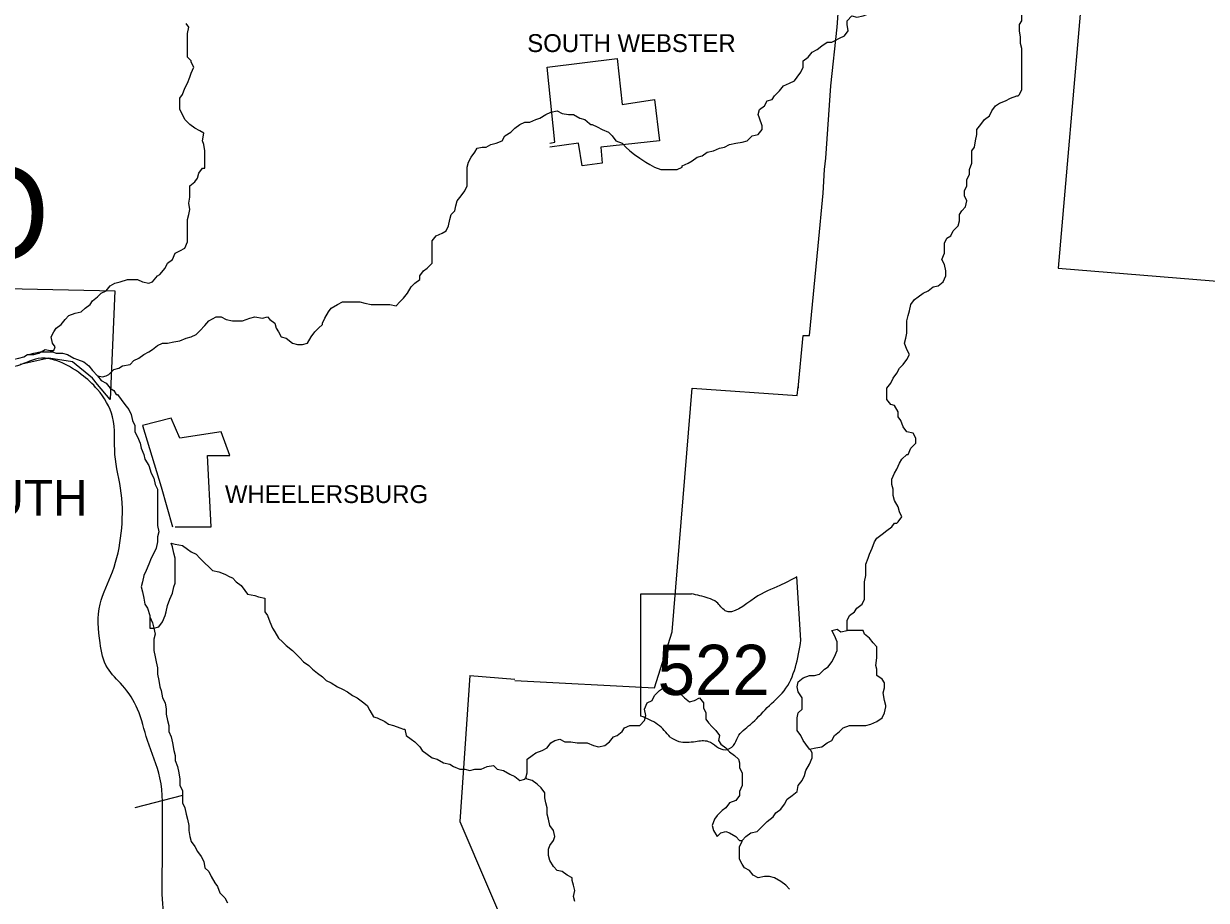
# Model space of a CAD drawing. Extents: x 0 to 40.2, y 0 to 22.
# Drawn here: x 6.366 to 7.657, y 15.911 to 16.868 of the extents above; entities that cross this region are included whole.
import ezdxf

# ---------------------------------------------------------------- set-up
doc = ezdxf.new("R2010")
doc.units = 0
doc.layers.add('Default', color=7, linetype='Continuous')
doc.layers.add('TR_Turning_Path1', color=7, linetype='Continuous')

msp = doc.modelspace()

# ---------------------------------------------------------------- linework, layer by layer
at = {"layer": 'Default'}
msp.add_line((7.0546, 16.1427), (7.0546, 16.1427), dxfattribs=at)
for points in [[(7.2114, 16.4699), (7.2169, 16.5272), (7.2237, 16.5272), (7.2332, 16.6253), (7.2387, 16.6826), (7.2401, 16.7085), (7.2414, 16.7208), (7.2469, 16.7998), (7.2537, 16.8639), (7.2578, 16.9198), (7.2578, 16.9198), (7.2578, 16.9198)], [(7.251, 16.8489), (7.2564, 16.8517), (7.2619, 16.8544), (7.266, 16.8598), (7.2646, 16.8667), (7.2646, 16.8707), (7.27, 16.8762), (7.2755, 16.8748), (7.2823, 16.8762), (7.2891, 16.8789), (7.2919, 16.883), (7.2973, 16.8844), (7.3055, 16.8871), (7.3109, 16.8885), (7.3164, 16.8926), (7.3164, 16.8994), (7.3219, 16.9035), (7.3232, 16.9103), (7.3246, 16.9116), (7.3246, 16.913)], [(7.4527, 16.7903), (7.4555, 16.7958), (7.4555, 16.8026), (7.4555, 16.8094), (7.4555, 16.8148), (7.4555, 16.8217), (7.4555, 16.8271), (7.4555, 16.8339), (7.4555, 16.8407), (7.4541, 16.8462), (7.4541, 16.853), (7.4527, 16.8598), (7.4527, 16.8667), (7.4555, 16.8707), (7.4555, 16.8789), (7.4555, 16.8844), (7.4527, 16.8885), (7.45, 16.8953), (7.4473, 16.9007), (7.4446, 16.9035), (7.4432, 16.9035)], [(7.5209, 16.8994), (7.495, 16.6008), (7.8468, 16.5722), (7.8372, 16.4385), (7.9054, 16.4331), (7.8918, 16.2599), (7.8849, 16.1645), (8.2163, 16.144), (8.2544, 16.1399), (8.3035, 16.1372)], [(6.5488, 16.8271), (6.5447, 16.8312), (6.5447, 16.838), (6.5447, 16.8435), (6.5447, 16.8517), (6.5447, 16.8571), (6.5461, 16.8639), (6.5433, 16.868)], [(7.1828, 16.7848), (7.1855, 16.7889), (7.191, 16.7944), (7.1951, 16.7998), (7.2019, 16.8026), (7.2073, 16.8053), (7.2101, 16.8094), (7.2141, 16.8148), (7.2169, 16.8203), (7.2169, 16.8271), (7.2223, 16.8312), (7.2264, 16.8367), (7.2319, 16.8394), (7.2373, 16.8435), (7.2428, 16.8476), (7.2482, 16.8476), (7.251, 16.8489)], [(6.5638, 16.7099), (6.5638, 16.7167), (6.5638, 16.7221), (6.5638, 16.7289), (6.5624, 16.7358), (6.5611, 16.7399), (6.5624, 16.748), (6.5583, 16.7508), (6.5529, 16.7535), (6.5474, 16.7576), (6.542, 16.763), (6.5393, 16.7685), (6.5365, 16.7739), (6.5365, 16.7794), (6.5365, 16.7862), (6.5393, 16.7903), (6.542, 16.7971), (6.5447, 16.8026), (6.5474, 16.8094), (6.5488, 16.8135), (6.5515, 16.8203), (6.5488, 16.8257), (6.5488, 16.8271)], [(6.9401, 16.7371), (6.9456, 16.7385), (6.9374, 16.8203), (7.0137, 16.8298), (7.0192, 16.7794), (7.0546, 16.7848), (7.0601, 16.7399), (6.996, 16.733), (6.9974, 16.7153), (6.9755, 16.7126), (6.9715, 16.7371), (6.9401, 16.733)], [(7.0846, 16.7126), (7.0914, 16.7153), (7.0955, 16.718), (7.101, 16.7221), (7.1064, 16.7235), (7.1119, 16.7276), (7.1187, 16.7289), (7.1255, 16.7317), (7.131, 16.733), (7.1364, 16.7358), (7.1432, 16.7371), (7.1501, 16.7385), (7.1555, 16.7399), (7.161, 16.7453), (7.1678, 16.7467), (7.1719, 16.7521), (7.1719, 16.7562), (7.1692, 16.7644), (7.1678, 16.7685), (7.1692, 16.7739), (7.1746, 16.778), (7.1773, 16.7835), (7.1828, 16.7848)], [(7.3778, 16.6362), (7.3805, 16.6417), (7.3859, 16.6471), (7.3873, 16.6526), (7.3873, 16.6594), (7.39, 16.6635), (7.3941, 16.6676), (7.3955, 16.6744), (7.3928, 16.6799), (7.3928, 16.6853), (7.3955, 16.6908), (7.3955, 16.6976), (7.3982, 16.703), (7.3982, 16.7085), (7.4009, 16.7153), (7.4009, 16.7221), (7.4009, 16.7289), (7.4037, 16.733), (7.405, 16.7399), (7.4064, 16.7467), (7.4064, 16.7521), (7.4105, 16.7576), (7.4146, 16.763), (7.42, 16.7671), (7.4227, 16.7726), (7.4268, 16.778), (7.4309, 16.7808), (7.4377, 16.7835), (7.4432, 16.7862), (7.45, 16.7889), (7.4514, 16.7889), (7.4527, 16.7903)], [(6.8706, 16.733), (6.876, 16.7358), (6.8815, 16.7371), (6.8883, 16.7399), (6.891, 16.7453), (6.8978, 16.7494), (6.9019, 16.7535), (6.9074, 16.7576), (6.9128, 16.7603), (6.9183, 16.7603), (6.9251, 16.763), (6.9292, 16.7644), (6.936, 16.7685), (6.9415, 16.7712), (6.9483, 16.7726), (6.9537, 16.7698), (6.9605, 16.7685), (6.966, 16.7685), (6.9728, 16.7644), (6.9783, 16.763), (6.9837, 16.7589), (6.9851, 16.7576), (6.9865, 16.7576)], [(6.9865, 16.7576), (6.9919, 16.7549), (6.9974, 16.7521), (7.0042, 16.7494), (7.0083, 16.7453), (7.0124, 16.7399), (7.0192, 16.7371), (7.0233, 16.733), (7.0274, 16.7289), (7.0328, 16.7249), (7.0383, 16.7208), (7.0451, 16.7167), (7.0492, 16.7139), (7.0546, 16.7112), (7.0614, 16.7085), (7.0683, 16.7085), (7.0737, 16.7085), (7.0792, 16.7085), (7.0846, 16.7112), (7.0846, 16.7126)], [(6.7983, 16.5926), (6.8024, 16.5981), (6.8065, 16.6008), (6.8119, 16.6062), (6.8119, 16.6131), (6.8119, 16.6185), (6.8119, 16.6253), (6.8119, 16.6308), (6.816, 16.6362), (6.8228, 16.639), (6.8269, 16.6417), (6.8297, 16.6471), (6.831, 16.654), (6.8324, 16.6594), (6.8365, 16.6635), (6.8378, 16.669), (6.8392, 16.6744), (6.8433, 16.6799), (6.8474, 16.6853), (6.8501, 16.6908), (6.8501, 16.699), (6.8501, 16.7044), (6.8501, 16.7112), (6.8515, 16.7167), (6.8542, 16.7221), (6.8583, 16.7276), (6.861, 16.7317), (6.8665, 16.733), (6.8706, 16.733)], [(6.5065, 16.5858), (6.512, 16.5926), (6.5147, 16.594), (6.5202, 16.6008), (6.5229, 16.6062), (6.5283, 16.6103), (6.5311, 16.6171), (6.5365, 16.6199), (6.542, 16.6226), (6.5447, 16.6294), (6.5447, 16.6349), (6.5447, 16.6417), (6.5447, 16.6471), (6.5447, 16.654), (6.5461, 16.6594), (6.5474, 16.6649), (6.5461, 16.6717), (6.5474, 16.6785), (6.5474, 16.684), (6.5474, 16.6908), (6.5529, 16.6949), (6.5556, 16.699), (6.557, 16.7044), (6.5611, 16.7099), (6.5638, 16.7099), (6.5638, 16.7099)], [(7.3259, 16.4958), (7.33, 16.5013), (7.3328, 16.5067), (7.33, 16.5122), (7.3273, 16.519), (7.3287, 16.5244), (7.33, 16.5299), (7.33, 16.5353), (7.33, 16.5435), (7.3314, 16.549), (7.3328, 16.5544), (7.3341, 16.5612), (7.3382, 16.5667), (7.3423, 16.5694), (7.3478, 16.5735), (7.3532, 16.5762), (7.3587, 16.5803), (7.3641, 16.5817), (7.3696, 16.5858), (7.3723, 16.5926), (7.3723, 16.5981), (7.3709, 16.6049), (7.3682, 16.6103), (7.3709, 16.6171), (7.3709, 16.6226), (7.3709, 16.6281), (7.3737, 16.6335), (7.3778, 16.6362)], [(6.3988, 16.5108), (6.4002, 16.5149), (6.3975, 16.519), (6.3961, 16.5258), (6.3988, 16.5312), (6.4015, 16.5353), (6.407, 16.5394), (6.4111, 16.5449), (6.4152, 16.549), (6.422, 16.5517), (6.4288, 16.5531), (6.4329, 16.5572), (6.4384, 16.5612), (6.4411, 16.5653), (6.4465, 16.5694), (6.4506, 16.5735), (6.4561, 16.5762), (6.4602, 16.5817), (6.4656, 16.5844), (6.4711, 16.5858), (6.4793, 16.5885), (6.4847, 16.5885), (6.4902, 16.5885), (6.4956, 16.5858), (6.5024, 16.5844), (6.5065, 16.5858), (6.5065, 16.5858)], [(6.692, 16.5408), (6.6947, 16.5462), (6.6988, 16.5531), (6.7015, 16.5572), (6.7083, 16.5612), (6.7138, 16.564), (6.7192, 16.564), (6.726, 16.564), (6.7329, 16.564), (6.7383, 16.5626), (6.7451, 16.5612), (6.7519, 16.5612), (6.7601, 16.5612), (6.7656, 16.5612), (6.7724, 16.5599), (6.7765, 16.564), (6.7806, 16.5681), (6.7847, 16.5735), (6.7888, 16.5803), (6.7928, 16.5844), (6.7983, 16.5885), (6.7983, 16.5912), (6.7983, 16.5926)], [(6.212, 16.5817), (6.4656, 16.5762), (6.4602, 16.4576), (6.4465, 16.474), (6.4411, 16.4808), (6.4193, 16.4985), (6.3934, 16.5026), (6.362, 16.4958)], [(6.4588, 16.4849), (6.4643, 16.4903), (6.4697, 16.4917), (6.4738, 16.4944), (6.482, 16.4958), (6.4861, 16.4999), (6.4915, 16.5026), (6.497, 16.5067), (6.5024, 16.5094), (6.5065, 16.5122), (6.512, 16.5163), (6.5174, 16.519), (6.5229, 16.519), (6.5297, 16.5203), (6.5365, 16.5217), (6.5433, 16.5244), (6.5488, 16.5258), (6.5542, 16.5285), (6.5583, 16.5326), (6.5638, 16.5381), (6.5679, 16.5435), (6.5761, 16.5476), (6.5761, 16.5476)], [(6.5761, 16.5476), (6.5815, 16.5476), (6.587, 16.5449), (6.5938, 16.5435), (6.5992, 16.5435), (6.6047, 16.5435), (6.6129, 16.5462), (6.6183, 16.5476), (6.6265, 16.5462), (6.632, 16.5476), (6.6347, 16.5449), (6.6401, 16.5408), (6.6415, 16.5353), (6.6442, 16.5312), (6.647, 16.5258), (6.6524, 16.5244), (6.6592, 16.519), (6.6647, 16.5176), (6.6701, 16.5176), (6.6756, 16.519), (6.6797, 16.5258), (6.6838, 16.5312), (6.6879, 16.5353), (6.692, 16.5394), (6.692, 16.5394), (6.692, 16.5408)], [(6.3716, 16.5067), (6.377, 16.5067), (6.3825, 16.5081), (6.3893, 16.5122), (6.3947, 16.5108), (6.3988, 16.5108)], [(6.2829, 16.4944), (6.2884, 16.4944), (6.2952, 16.4944), (6.302, 16.4958), (6.3088, 16.4958), (6.3157, 16.4958), (6.3211, 16.4985), (6.3266, 16.4985), (6.3347, 16.4999), (6.3402, 16.4999), (6.347, 16.4999), (6.3538, 16.5013), (6.3606, 16.5026), (6.3661, 16.504), (6.3702, 16.5067), (6.3716, 16.5067)], [(6.3716, 16.5067), (6.377, 16.5081), (6.3838, 16.5094), (6.3893, 16.5094), (6.3975, 16.5094), (6.4015, 16.5081), (6.4084, 16.5081), (6.4138, 16.5067), (6.4206, 16.5026), (6.4247, 16.5013), (6.4315, 16.4985), (6.437, 16.4944), (6.4411, 16.489), (6.4465, 16.4835), (6.4465, 16.4835)], [(7.3314, 16.3976), (7.3341, 16.4045), (7.3396, 16.4099), (7.3396, 16.4154), (7.3369, 16.4208), (7.33, 16.4222), (7.3259, 16.4276), (7.3232, 16.4344), (7.3205, 16.4385), (7.3205, 16.444), (7.3164, 16.4508), (7.3123, 16.4522), (7.3082, 16.4576), (7.3082, 16.4631), (7.3082, 16.4699), (7.3123, 16.4753), (7.315, 16.4808), (7.3191, 16.4863), (7.3219, 16.4917), (7.3246, 16.4944), (7.3259, 16.4958)], [(6.4465, 16.4835), (6.452, 16.4822), (6.4561, 16.4835), (6.4588, 16.4849)], [(6.4465, 16.4835), (6.4506, 16.4781), (6.4561, 16.4753), (6.4602, 16.4699), (6.4643, 16.4672), (6.467, 16.4631), (6.4684, 16.4631)], [(6.4684, 16.4631), (6.4724, 16.4576), (6.4765, 16.4522), (6.4806, 16.4467), (6.4834, 16.4413), (6.4847, 16.4344), (6.4874, 16.429), (6.4874, 16.4222), (6.4902, 16.4167), (6.4929, 16.4099), (6.4943, 16.4045), (6.497, 16.3976), (6.4983, 16.3922), (6.5024, 16.3854), (6.5052, 16.3772)], [(7.0737, 16.204), (7.0955, 16.4699)], [(7.0955, 16.4699), (7.2101, 16.4617)], [(7.2101, 16.4617), (7.2114, 16.4713), (7.2114, 16.4699)], [(6.5311, 16.3186), (6.5706, 16.3186), (6.5665, 16.3963), (6.5911, 16.3963), (6.5815, 16.4222), (6.5365, 16.4154), (6.527, 16.4372), (6.4956, 16.429), (6.5161, 16.3622), (6.5283, 16.3186)], [(7.3205, 16.324), (7.3246, 16.3295), (7.3219, 16.3349), (7.3205, 16.3404), (7.3164, 16.3472), (7.315, 16.3526), (7.315, 16.3595), (7.3137, 16.3649), (7.3137, 16.3704), (7.3164, 16.3772), (7.3191, 16.3813), (7.3219, 16.3881), (7.3246, 16.3922), (7.33, 16.3976), (7.3314, 16.3976)], [(6.5052, 16.3772), (6.5079, 16.3717), (6.5093, 16.3649), (6.512, 16.3595), (6.512, 16.3526), (6.512, 16.3472), (6.512, 16.3404), (6.512, 16.3336), (6.512, 16.3281), (6.512, 16.3199), (6.5133, 16.3131), (6.512, 16.3076), (6.512, 16.3022), (6.5106, 16.2954), (6.5079, 16.2899), (6.5052, 16.2845), (6.5024, 16.2777), (6.4997, 16.2708), (6.497, 16.2654), (6.4956, 16.2586), (6.4943, 16.2531), (6.4956, 16.2477), (6.497, 16.2408), (6.4983, 16.234), (6.5011, 16.2299), (6.5038, 16.2218), (6.5038, 16.2218), (6.5038, 16.2204)], [(7.2646, 16.2054), (7.2646, 16.2122), (7.2646, 16.2163), (7.2673, 16.2218), (7.2728, 16.2258), (7.2755, 16.2299), (7.281, 16.234), (7.2837, 16.2395), (7.2837, 16.2463), (7.2837, 16.2531), (7.2837, 16.2586), (7.285, 16.2654), (7.285, 16.2708), (7.285, 16.2777), (7.2878, 16.2845), (7.2891, 16.2886), (7.2919, 16.2954), (7.2946, 16.3022), (7.2973, 16.3063), (7.3028, 16.3104), (7.3082, 16.3145), (7.3137, 16.3186), (7.3164, 16.3226), (7.3191, 16.3226), (7.3205, 16.324)], [(6.5038, 16.2204), (6.5038, 16.2136), (6.5038, 16.2081), (6.5079, 16.2081), (6.5133, 16.2095), (6.5174, 16.2149), (6.5202, 16.2218), (6.5215, 16.2258), (6.5229, 16.2327), (6.5256, 16.2395), (6.5283, 16.2463), (6.5297, 16.2531), (6.5311, 16.2572), (6.5311, 16.264), (6.5311, 16.2708), (6.5311, 16.2777), (6.5311, 16.2845), (6.5297, 16.2899), (6.5283, 16.2967), (6.527, 16.3008)], [(6.527, 16.3008), (6.5311, 16.2995), (6.5393, 16.2981), (6.5447, 16.294), (6.5488, 16.2913), (6.5542, 16.2886), (6.5583, 16.2845), (6.5638, 16.279), (6.5679, 16.2749), (6.572, 16.2708), (6.5788, 16.2695), (6.5856, 16.2667), (6.5911, 16.264), (6.5938, 16.2627)], [(6.5938, 16.2627), (6.5979, 16.2586), (6.6033, 16.2545), (6.6074, 16.249), (6.6101, 16.2449), (6.6183, 16.2436), (6.6224, 16.2422), (6.6292, 16.2408), (6.6292, 16.2327), (6.6292, 16.2258), (6.632, 16.2218), (6.6347, 16.2149), (6.6374, 16.2081), (6.6401, 16.204), (6.6442, 16.1972), (6.6483, 16.1931), (6.6524, 16.189), (6.6592, 16.1836), (6.662, 16.1809), (6.6674, 16.1754), (6.6715, 16.1713), (6.677, 16.1672), (6.677, 16.1672)], [(7.2143, 16.1948), (7.2097, 16.2638)], [(7.0395, 16.112), (7.0395, 16.2454), (7.0947, 16.2454)], [(6.5038, 16.2204), (6.5065, 16.2136), (6.5079, 16.2081), (6.5093, 16.2013), (6.5079, 16.1958), (6.5079, 16.189), (6.5079, 16.1836), (6.5093, 16.1768), (6.5106, 16.1713), (6.512, 16.1645), (6.512, 16.1577), (6.5133, 16.1509), (6.5147, 16.144), (6.5161, 16.1399), (6.5174, 16.1318), (6.5202, 16.1263), (6.5215, 16.1195), (6.5215, 16.114), (6.5229, 16.1072), (6.5243, 16.1018), (6.5243, 16.095), (6.527, 16.0895), (6.5283, 16.0827), (6.5297, 16.0745), (6.5311, 16.0691), (6.5311, 16.0636), (6.5338, 16.0568), (6.5352, 16.05), (6.5365, 16.0431), (6.5365, 16.0363), (6.5393, 16.0309), (6.5393, 16.0254), (6.5393, 16.0172), (6.542, 16.0118), (6.5433, 16.005), (6.5447, 15.9995), (6.5461, 15.9927), (6.5461, 15.9872), (6.5474, 15.9804), (6.5488, 15.975), (6.5529, 15.9695)], [(7.0546, 16.1427), (7.0737, 16.204), (7.0737, 16.204)], [(7.2237, 16.0759), (7.2196, 16.0813), (7.2169, 16.0854), (7.2141, 16.0909), (7.2101, 16.0963), (7.2101, 16.1018), (7.2101, 16.11), (7.2114, 16.1154), (7.2155, 16.1195), (7.2155, 16.1263), (7.2155, 16.1318), (7.2114, 16.1386), (7.2101, 16.144), (7.2114, 16.1495), (7.2169, 16.1536), (7.2237, 16.1563), (7.2291, 16.1563), (7.2346, 16.1577), (7.2401, 16.1631), (7.2441, 16.1659), (7.2482, 16.1713), (7.251, 16.1768), (7.2537, 16.1836), (7.2537, 16.189), (7.2537, 16.1931), (7.251, 16.1999), (7.2482, 16.2054), (7.2537, 16.2068), (7.2578, 16.204), (7.2646, 16.2054), (7.2646, 16.2054)], [(7.3069, 16.1236), (7.3055, 16.129), (7.3041, 16.1372), (7.3055, 16.1427), (7.3055, 16.1481), (7.3028, 16.1522), (7.2973, 16.1563), (7.2973, 16.1631), (7.296, 16.1672), (7.2973, 16.1754), (7.2973, 16.1809), (7.2973, 16.1877), (7.2932, 16.1918), (7.2891, 16.1972), (7.2837, 16.2013), (7.2823, 16.2054), (7.2769, 16.2054), (7.2728, 16.2054), (7.266, 16.2054), (7.2646, 16.2054), (7.2646, 16.2054)], [(6.677, 16.1672), (6.681, 16.1631), (6.6865, 16.159), (6.692, 16.1549), (6.696, 16.1509), (6.7015, 16.1481), (6.7083, 16.144), (6.7138, 16.1413), (6.7192, 16.1386), (6.7247, 16.1345), (6.7301, 16.1318), (6.7356, 16.1277), (6.741, 16.1236), (6.7438, 16.1181), (6.7479, 16.1113), (6.7519, 16.11), (6.7601, 16.1059), (6.7642, 16.1031), (6.7697, 16.1018), (6.7765, 16.099), (6.7806, 16.0977), (6.7819, 16.0977)], [(6.8528, 16.1563), (6.8419, 15.9968), (6.9346, 15.78), (6.6647, 15.66)], [(6.8528, 16.1563), (6.9019, 16.1522), (6.9019, 16.1522)], [(6.9019, 16.1509), (7.0546, 16.1427)], [(6.981, 16.0827), (6.9878, 16.08), (6.9933, 16.0786), (7.0001, 16.08), (7.0055, 16.084), (7.0096, 16.0895), (7.0137, 16.0909), (7.0192, 16.095), (7.0219, 16.099), (7.0274, 16.1018), (7.0328, 16.1018), (7.0383, 16.1018), (7.0437, 16.1072), (7.0451, 16.1127), (7.0437, 16.1195), (7.0464, 16.1263), (7.0519, 16.129), (7.0546, 16.1345), (7.0601, 16.1399), (7.0601, 16.1399), (7.0601, 16.1399)], [(7.0601, 16.1399), (7.0642, 16.1427), (7.071, 16.1427), (7.0764, 16.1399), (7.0819, 16.1372), (7.0873, 16.1318), (7.0928, 16.1277), (7.0983, 16.129), (7.1037, 16.1318), (7.1078, 16.1263), (7.1078, 16.1209), (7.1105, 16.1154), (7.1105, 16.1086), (7.1133, 16.1045), (7.1173, 16.1004), (7.1214, 16.0963), (7.1255, 16.0909), (7.1242, 16.0854), (7.1269, 16.0813), (7.1323, 16.0772), (7.1364, 16.0731), (7.1419, 16.0691), (7.146, 16.065), (7.1473, 16.0609), (7.1473, 16.0609)], [(7.2237, 16.0759), (7.2305, 16.0772), (7.2373, 16.0786), (7.2428, 16.0827), (7.2482, 16.0854), (7.251, 16.0909), (7.2564, 16.095), (7.2605, 16.099), (7.2673, 16.1018), (7.2728, 16.1018), (7.2796, 16.1018), (7.285, 16.1018), (7.2905, 16.1031), (7.2973, 16.1059), (7.3028, 16.11), (7.3055, 16.1154), (7.3069, 16.1222), (7.3069, 16.1236)], [(6.7819, 16.0977), (6.7833, 16.0909), (6.7888, 16.0868), (6.7928, 16.084), (6.7983, 16.0786), (6.801, 16.0745), (6.8065, 16.0704), (6.8119, 16.0663), (6.8174, 16.065), (6.8242, 16.0609), (6.831, 16.0595), (6.8351, 16.0568), (6.8419, 16.0541), (6.8474, 16.0541)], [(6.9142, 16.0445), (6.9156, 16.05), (6.9156, 16.0568), (6.9156, 16.065), (6.921, 16.0691), (6.9251, 16.0718), (6.9319, 16.0745), (6.9374, 16.0772), (6.9415, 16.0827), (6.9456, 16.0854), (6.951, 16.0868), (6.9565, 16.084), (6.9633, 16.084), (6.9701, 16.0827), (6.9769, 16.0827), (6.9796, 16.0827), (6.981, 16.0827)], [(7.1501, 15.9763), (7.1542, 15.9804), (7.1596, 15.9845), (7.1664, 15.9859), (7.1705, 15.99), (7.1746, 15.9941), (7.1773, 15.9968), (7.1841, 16.0022), (7.1869, 16.0063), (7.1923, 16.0104), (7.1964, 16.0159), (7.1991, 16.0213), (7.2046, 16.0254), (7.2101, 16.0295), (7.2114, 16.0363), (7.2155, 16.0418), (7.2182, 16.0472), (7.2196, 16.0527), (7.2237, 16.0595), (7.2264, 16.0663), (7.2264, 16.0718), (7.2251, 16.0745), (7.2237, 16.0759)], [(7.1473, 16.0609), (7.1473, 16.0554), (7.1501, 16.05), (7.1501, 16.0418), (7.1501, 16.0363), (7.1473, 16.0295), (7.1473, 16.0254), (7.1432, 16.02), (7.1364, 16.0172), (7.1323, 16.0118), (7.1282, 16.0091), (7.1228, 16.0036), (7.1201, 15.9995), (7.1173, 15.9927), (7.1187, 15.9872), (7.1228, 15.9804), (7.1269, 15.9845), (7.1323, 15.9859), (7.1364, 15.9845), (7.1432, 15.9804), (7.1473, 15.9763), (7.1501, 15.9763)], [(6.8474, 16.0541), (6.8528, 16.0527), (6.8583, 16.0541), (6.8651, 16.0541), (6.8719, 16.0568), (6.8787, 16.0581), (6.8828, 16.0541), (6.8897, 16.0527), (6.8965, 16.0486), (6.9019, 16.0459), (6.9074, 16.0418), (6.9128, 16.0431), (6.9142, 16.0445)], [(6.9646, 15.9354), (6.9592, 15.9382), (6.9537, 15.9423), (6.9483, 15.9436), (6.9442, 15.9477), (6.9401, 15.9545), (6.9387, 15.96), (6.9387, 15.9668), (6.9401, 15.9709), (6.9442, 15.9763), (6.9456, 15.9804), (6.9442, 15.9872), (6.9401, 15.9927), (6.9387, 15.9995), (6.9374, 16.005), (6.9374, 16.0118), (6.936, 16.0172), (6.9346, 16.0227), (6.9346, 16.0281), (6.9306, 16.0336), (6.9265, 16.0377), (6.921, 16.0418), (6.9156, 16.0431), (6.9142, 16.0445)], [(6.5393, 16.0254), (6.4874, 16.0118)], [(6.5529, 15.9695), (6.5556, 15.9641), (6.5597, 15.9586), (6.5624, 15.9532), (6.5638, 15.9463), (6.5679, 15.9423), (6.5706, 15.9368), (6.5747, 15.93), (6.5774, 15.9259), (6.5802, 15.9191), (6.5856, 15.9136), (6.5883, 15.9082)], [(7.2019, 15.9232), (7.1978, 15.9273), (7.1923, 15.9313), (7.1855, 15.9354), (7.1801, 15.9368), (7.1746, 15.9368), (7.1678, 15.9354), (7.1623, 15.9382), (7.1582, 15.9436), (7.1528, 15.9463), (7.1501, 15.9504), (7.1473, 15.9559), (7.1473, 15.9627), (7.1473, 15.9695), (7.1501, 15.975), (7.1501, 15.9763)], [(6.9674, 15.9095), (6.966, 15.915), (6.9674, 15.9218), (6.966, 15.9273), (6.9646, 15.9327), (6.9646, 15.9354)]]:
    msp.add_lwpolyline(points, dxfattribs=at)
for points in [[(6.6647, 15.66), (6.6347, 15.6791), (6.6101, 15.6982), (6.5788, 15.7227), (6.5583, 15.7596), (6.5447, 15.795), (6.5324, 15.8264), (6.5229, 15.8727), (6.5174, 15.9123), (6.5174, 15.9545), (6.5174, 15.9927), (6.5147, 16.0445), (6.5011, 16.0854), (6.4902, 16.1195), (6.4738, 16.1454), (6.4574, 16.1645), (6.4493, 16.1918), (6.4493, 16.234), (6.4629, 16.2695), (6.4724, 16.3117), (6.4724, 16.3554), (6.4656, 16.3976), (6.4629, 16.4385), (6.4465, 16.4685), (6.4288, 16.4849), (6.4015, 16.4999), (6.3852, 16.5026), (6.3593, 16.4944), (6.3456, 16.4917), (6.3102, 16.4822), (6.2734, 16.474), (6.2393, 16.4576), (6.212, 16.4385), (6.1861, 16.4222), (6.1548, 16.4045), (6.1289, 16.3895), (6.1098, 16.3785), (6.0866, 16.3704), (6.0511, 16.3717), (6.0171, 16.3785), (5.983, 16.3813), (5.9448, 16.3881), (5.9189, 16.3704), (5.8957, 16.3526), (5.8766, 16.3117), (5.8589, 16.2872), (5.8357, 16.2517), (5.8166, 16.2177), (5.7935, 16.2081), (5.7539, 16.1918), (5.7212, 16.1754), (5.6803, 16.1631), (5.653, 16.1481), (5.6162, 16.1318), (5.5944, 16.1018), (5.5821, 16.0772), (5.5685, 16.0418), (5.559, 16.0077), (5.5562, 15.9668), (5.5249, 15.9382), (5.4908, 15.9123), (5.4431, 15.8891), (5.3926, 15.8891), (5.3517, 15.8809), (5.3067, 15.8809), (5.2631, 15.8864), (5.2222, 15.9054), (5.1963, 15.9232), (5.1622, 15.93), (5.1363, 15.9313), (5.1186, 15.915), (5.0845, 15.9041), (5.0613, 15.8864)], [(7.2097, 16.2638), (7.1913, 16.2546), (7.1637, 16.2408), (7.1315, 16.227), (7.1223, 16.2362), (7.1131, 16.2408), (7.0947, 16.2454)], [(7.0717, 16.089), (7.0809, 16.0844), (7.0993, 16.0844), (7.1131, 16.0844), (7.1315, 16.0752), (7.1407, 16.0798), (7.1453, 16.089), (7.1591, 16.1028), (7.1775, 16.1212), (7.1959, 16.1396), (7.2143, 16.1948)], [(7.0717, 16.089), (7.0579, 16.1028), (7.0395, 16.112)]]:
    msp.add_spline(points, degree=3, dxfattribs=at)

# ---------------------------------------------------------------- texts
for s, height, p in [('SOUTH WEBSTER', 0.019502, (6.9156, 16.8367)), ('PORTSMOUTH', 0.039, (6.0648, 16.3308)), ('WHEELERSBURG', 0.019502, (6.5856, 16.3445)), ('522', 0.05486, (7.0579, 16.135))]:
    msp.add_text(s, height=height, dxfattribs=at).set_placement(p)
at = {"layer": 'TR_Turning_Path1'}
msp.add_text('S   C   I   O   T   O', height=0.101489, dxfattribs=at).set_placement((5.3081, 16.6103))

doc.saveas('drawing.dxf')
